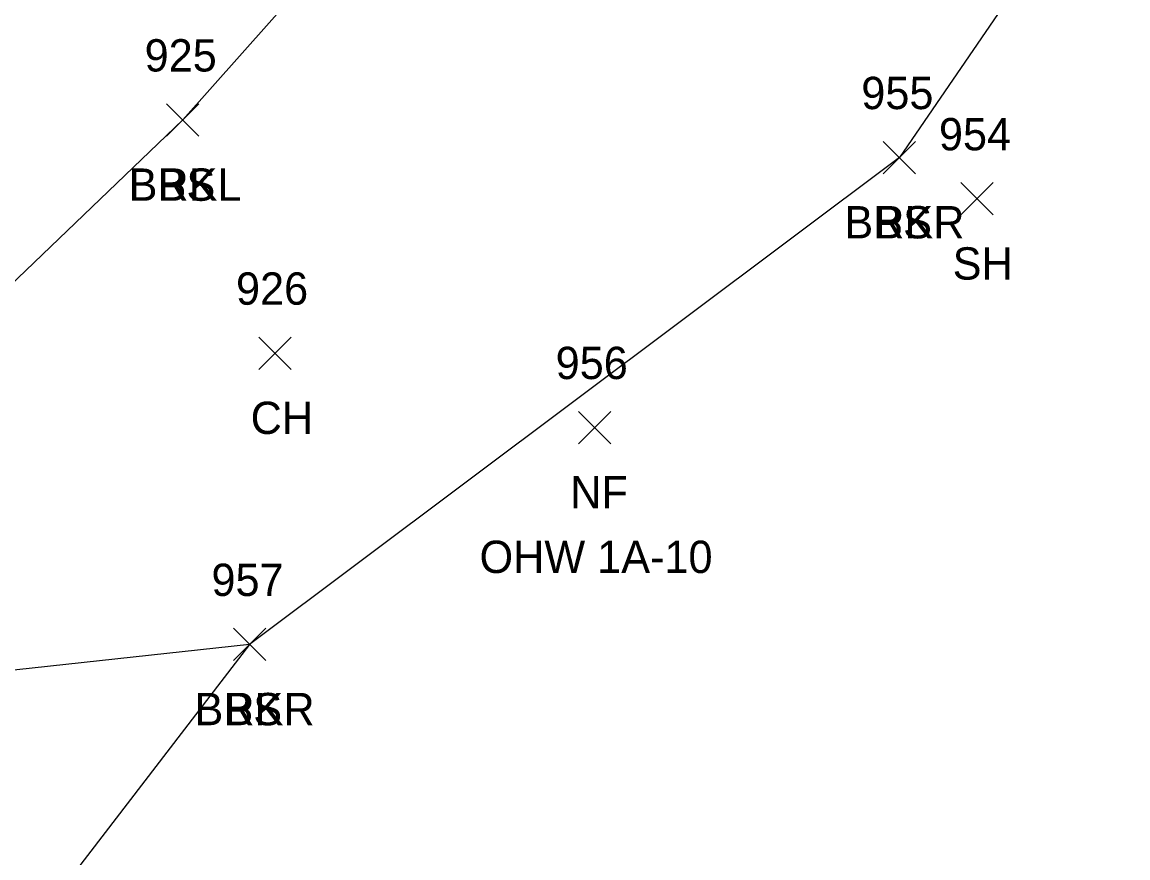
# Model space of a CAD drawing. Extents: x 1528286 to 1556263, y 492387 to 508952.
# Drawn here: x 1528472.8 to 1528541.2, y 492537.5 to 492589.2 of the extents above; entities that cross this region are included whole.
import ezdxf

# ---------------------------------------------------------------- set-up
doc = ezdxf.new("R2010")
doc.units = 0
for name, color, linetype in [('L_A', 7, 'Continuous'), ('L_C', 7, 'Continuous'), ('L_I', 7, 'Continuous'), ('L_TIC', 7, 'Continuous'), ('LAWE', 7, 'Continuous'), ('LELB', 7, 'Continuous')]:
    doc.layers.add(name, color=color, linetype=linetype)

msp = doc.modelspace()

# ---------------------------------------------------------------- linework, layer by layer
at = {"layer": 'L_TIC'}
for points in [[(1528481.777, 492582.151), (1528483.777, 492584.151)], [(1528483.777, 492582.151), (1528481.777, 492584.151)], [(1528481.777, 492582.151), (1528483.777, 492584.151)], [(1528483.777, 492582.151), (1528481.777, 492584.151)], [(1528481.777, 492582.151), (1528483.777, 492584.151)], [(1528483.777, 492582.151), (1528481.777, 492584.151)], [(1528481.777, 492582.151), (1528483.777, 492584.151)], [(1528483.777, 492582.151), (1528481.777, 492584.151)], [(1528526.115, 492579.823), (1528528.115, 492581.823)], [(1528528.115, 492579.823), (1528526.115, 492581.823)], [(1528526.115, 492579.823), (1528528.115, 492581.823)], [(1528528.115, 492579.823), (1528526.115, 492581.823)], [(1528526.115, 492579.823), (1528528.115, 492581.823)], [(1528528.115, 492579.823), (1528526.115, 492581.823)], [(1528526.115, 492579.823), (1528528.115, 492581.823)], [(1528528.115, 492579.823), (1528526.115, 492581.823)], [(1528530.918, 492577.273), (1528532.918, 492579.273)], [(1528532.918, 492577.273), (1528530.918, 492579.273)], [(1528530.918, 492577.273), (1528532.918, 492579.273)], [(1528532.918, 492577.273), (1528530.918, 492579.273)], [(1528487.484, 492567.719), (1528489.484, 492569.719)], [(1528489.484, 492567.719), (1528487.484, 492569.719)], [(1528487.484, 492567.719), (1528489.484, 492569.719)], [(1528489.484, 492567.719), (1528487.484, 492569.719)], [(1528507.26, 492563.117), (1528509.26, 492565.117)], [(1528509.26, 492563.117), (1528507.26, 492565.117)], [(1528507.26, 492563.117), (1528509.26, 492565.117)], [(1528509.26, 492563.117), (1528507.26, 492565.117)], [(1528485.911, 492549.694), (1528487.911, 492551.694)], [(1528487.911, 492549.694), (1528485.911, 492551.694)], [(1528485.911, 492549.694), (1528487.911, 492551.694)], [(1528487.911, 492549.694), (1528485.911, 492551.694)], [(1528485.911, 492549.694), (1528487.911, 492551.694)], [(1528487.911, 492549.694), (1528485.911, 492551.694)], [(1528485.911, 492549.694), (1528487.911, 492551.694)], [(1528487.911, 492549.694), (1528485.911, 492551.694)]]:
    msp.add_lwpolyline(points, dxfattribs=at)
at = {"layer": 'LAWE'}
for points in [[(1528639.893, 492735.148), (1528628.638, 492716.197), (1528619.322, 492697.772), (1528600.014, 492685.78), (1528586.494, 492675.208), (1528555.765, 492651.711), (1528552.059, 492644.142), (1528537.626, 492632.534), (1528523.345, 492621.851), (1528510.87, 492609.533), (1528497.291, 492599.489), (1528482.777, 492583.151), (1528460.774, 492562.048), (1528436.992, 492551.704), (1528418.951, 492545.204), (1528399.482, 492529.93), (1528387.952, 492519.312), (1528358.196, 492480.955)], [(1528639.893, 492735.148), (1528628.638, 492716.197), (1528619.322, 492697.772), (1528600.014, 492685.78), (1528586.494, 492675.208), (1528555.765, 492651.711), (1528552.059, 492644.142), (1528537.626, 492632.534), (1528523.345, 492621.851), (1528510.87, 492609.533), (1528497.291, 492599.489), (1528482.777, 492583.151), (1528460.774, 492562.048), (1528436.992, 492551.704), (1528418.951, 492545.204), (1528399.482, 492529.93), (1528387.952, 492519.312), (1528358.196, 492480.955)], [(1528645.438, 492730.638), (1528651.622, 492718.642), (1528645.743, 492704.772), (1528631.806, 492684.8), (1528615.475, 492671.091), (1528597.131, 492648.324), (1528570.323, 492633.929), (1528549.926, 492614.136), (1528527.115, 492580.823), (1528486.911, 492550.694), (1528466.236, 492548.442), (1528453.392, 492536.119), (1528428.919, 492520.065), (1528405.493, 492507.44), (1528391.912, 492487.091), (1528384.545, 492464.65)], [(1528645.438, 492730.638), (1528651.622, 492718.642), (1528645.743, 492704.772), (1528631.806, 492684.8), (1528615.475, 492671.091), (1528597.131, 492648.324), (1528570.323, 492633.929), (1528549.926, 492614.136), (1528527.115, 492580.823), (1528486.911, 492550.694), (1528466.236, 492548.442), (1528453.392, 492536.119), (1528428.919, 492520.065), (1528405.493, 492507.44), (1528391.912, 492487.091), (1528384.545, 492464.65)]]:
    msp.add_lwpolyline(points, dxfattribs=at)
at = {"layer": 'LELB'}
for points in [[(1528653.271, 492717.805), (1528645.743, 492704.772), (1528631.806, 492684.8), (1528615.475, 492671.091), (1528597.131, 492648.324), (1528570.323, 492633.929), (1528549.926, 492614.136), (1528527.115, 492580.823), (1528486.911, 492550.694), (1528472.867, 492532.388)], [(1528653.271, 492717.805), (1528645.743, 492704.772), (1528631.806, 492684.8), (1528615.475, 492671.091), (1528597.131, 492648.324), (1528570.323, 492633.929), (1528549.926, 492614.136), (1528527.115, 492580.823), (1528486.911, 492550.694), (1528472.867, 492532.388)], [(1528619.629, 492709.303), (1528607.886, 492695.261), (1528600.014, 492685.78), (1528586.494, 492675.208), (1528555.765, 492651.711), (1528552.059, 492644.142), (1528537.626, 492632.534), (1528523.345, 492621.851), (1528510.87, 492609.533), (1528497.291, 492599.489), (1528482.777, 492583.151), (1528460.774, 492562.048), (1528436.992, 492551.704), (1528418.951, 492545.204), (1528399.482, 492529.93), (1528387.952, 492519.312), (1528358.196, 492480.955)], [(1528619.629, 492709.303), (1528607.886, 492695.261), (1528600.014, 492685.78), (1528586.494, 492675.208), (1528555.765, 492651.711), (1528552.059, 492644.142), (1528537.626, 492632.534), (1528523.345, 492621.851), (1528510.87, 492609.533), (1528497.291, 492599.489), (1528482.777, 492583.151), (1528460.774, 492562.048), (1528436.992, 492551.704), (1528418.951, 492545.204), (1528399.482, 492529.93), (1528387.952, 492519.312), (1528358.196, 492480.955)]]:
    msp.add_lwpolyline(points, dxfattribs=at)

# ---------------------------------------------------------------- texts
at = {"layer": 'L_A'}
for s, p in [('BRKL', (1528479.423, 492578.151)), ('BRKL', (1528479.423, 492578.151)), ('BS', (1528481.218, 492578.151)), ('BS', (1528481.218, 492578.151)), ('BRKR', (1528523.706, 492575.823)), ('BRKR', (1528523.706, 492575.823)), ('BS', (1528525.556, 492575.823)), ('BS', (1528525.556, 492575.823)), ('SH', (1528530.406, 492573.273)), ('SH', (1528530.406, 492573.273)), ('CH', (1528486.973, 492563.719)), ('CH', (1528486.973, 492563.719)), ('NF', (1528506.741, 492559.117)), ('NF', (1528506.741, 492559.117)), ('BRKR', (1528483.501, 492545.694)), ('BRKR', (1528483.501, 492545.694)), ('BS', (1528485.352, 492545.694)), ('BS', (1528485.352, 492545.694))]:
    msp.add_text(s, height=2, dxfattribs=at).set_placement(p)
at = {"layer": 'L_C'}
msp.add_text('OHW 1A-10', height=2, dxfattribs=at).set_placement((1528501.134, 492555.117))
msp.add_text('OHW 1A-10', height=2, dxfattribs=at).set_placement((1528501.134, 492555.117))
at = {"layer": 'L_I'}
for s, p in [('925', (1528480.415, 492586.151)), ('925', (1528480.415, 492586.151)), ('925', (1528480.415, 492586.151)), ('925', (1528480.415, 492586.151)), ('955', (1528524.753, 492583.823)), ('955', (1528524.753, 492583.823)), ('955', (1528524.753, 492583.823)), ('955', (1528524.753, 492583.823)), ('954', (1528529.556, 492581.273)), ('954', (1528529.556, 492581.273)), ('926', (1528486.067, 492571.719)), ('926', (1528486.067, 492571.719)), ('956', (1528505.843, 492567.117)), ('956', (1528505.843, 492567.117)), ('957', (1528484.549, 492553.694)), ('957', (1528484.549, 492553.694)), ('957', (1528484.549, 492553.694)), ('957', (1528484.549, 492553.694))]:
    msp.add_text(s, height=2, dxfattribs=at).set_placement(p)

doc.saveas('drawing.dxf')
